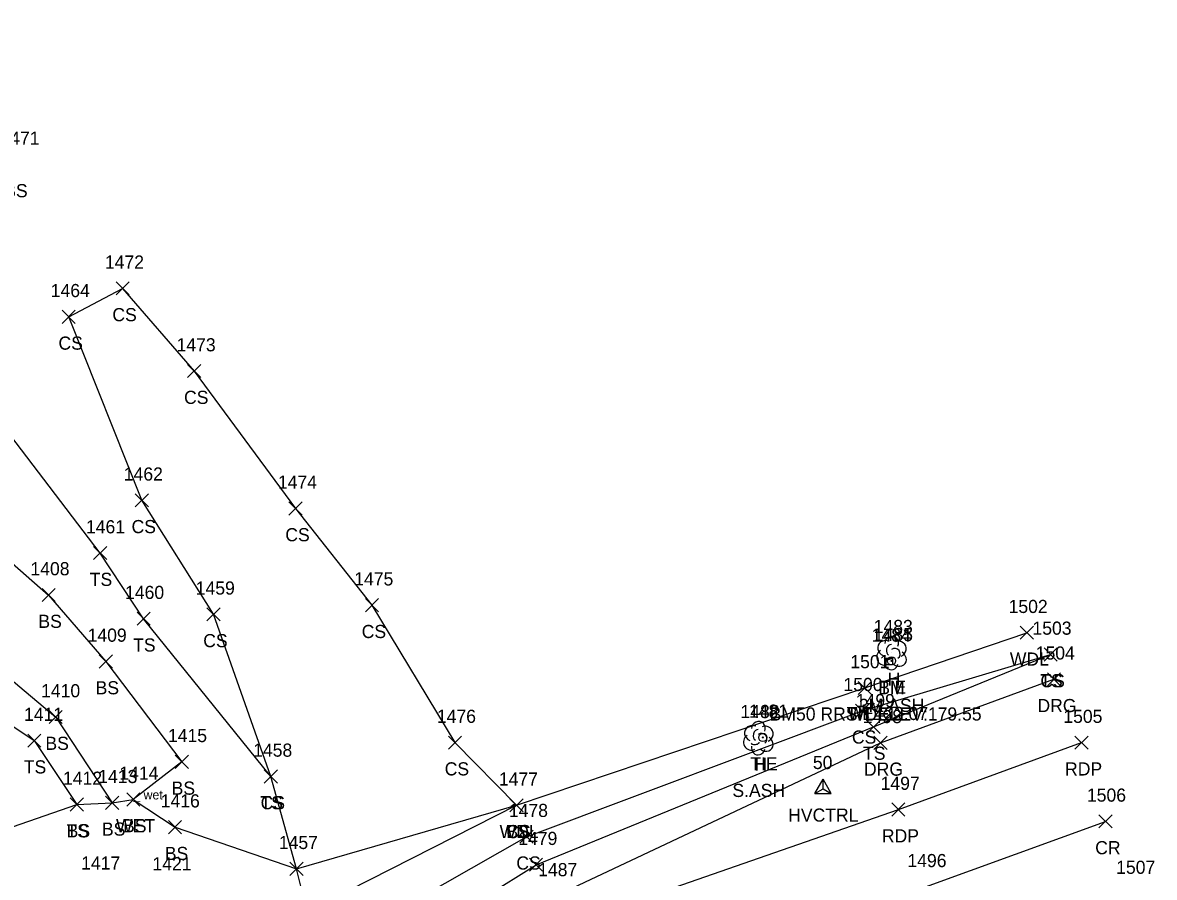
# Model space of a CAD drawing. Extents: x 1443064 to 1445163, y 544063 to 544655.
# Drawn here: x 1443666.1 to 1443838.4, y 544343.6 to 544473.7 of the extents above; entities that cross this region are included whole.
import ezdxf

# ---------------------------------------------------------------- set-up
doc = ezdxf.new("R2010")
doc.units = 0
for name, color, linetype in [('C_A', 7, 'Continuous'), ('C_C', 7, 'Continuous'), ('C_I', 7, 'Continuous'), ('CBP', 7, 'Continuous'), ('CPBM', 7, 'Continuous'), ('CPSM', 7, 'Continuous'), ('L_A', 7, 'Continuous'), ('L_C', 7, 'Continuous'), ('L_I', 7, 'Continuous'), ('L_TIC', 7, 'Continuous'), ('LAWA', 7, 'Continuous'), ('LELB', 7, 'Continuous'), ('LTD', 7, 'Continuous'), ('LWET', 7, 'Continuous'), ('P_A', 7, 'Continuous'), ('P_I', 7, 'Continuous'), ('P_TIC', 7, 'Continuous'), ('PET', 7, 'Continuous'), ('PRC', 7, 'Continuous'), ('R_A', 7, 'Continuous'), ('R_I', 7, 'Continuous'), ('R_TIC', 7, 'Continuous'), ('RDG', 7, 'Continuous')]:
    doc.layers.add(name, color=color, linetype=linetype)

msp = doc.modelspace()

# ---------------------------------------------------------------- linework, layer by layer
at = {"layer": 'CBP'}
for centre, radius in [((1443798.39, 544376.58), 0.625), ((1443798.39, 544376.58), 0.0833), ((1443778.81, 544364.93), 0.625), ((1443778.81, 544364.93), 0.0833)]:
    msp.add_circle(centre, radius, dxfattribs=at)
at = {"layer": 'CPBM'}
for p, q in [((1443797.56, 544376), (1443797.56, 544377)), ((1443797.56, 544377), (1443798.56, 544377)), ((1443798.56, 544376), (1443797.56, 544376)), ((1443798.06, 544376.5), (1443798.06, 544376.5)), ((1443798.06, 544376.5), (1443798.06, 544376.5)), ((1443798.56, 544377), (1443798.56, 544376))]:
    msp.add_line(p, q, dxfattribs=at)
at = {"layer": 'CPSM'}
for p, q in [((1443786.72, 544356.4), (1443787.97, 544358.57)), ((1443789.22, 544356.4), (1443787.97, 544358.57)), ((1443787.97, 544357.12), (1443787.97, 544358.57)), ((1443786.72, 544356.4), (1443787.97, 544357.12)), ((1443787.97, 544357.12), (1443787.97, 544357.12)), ((1443787.97, 544357.12), (1443789.22, 544356.4)), ((1443786.72, 544356.4), (1443789.22, 544356.4))]:
    msp.add_line(p, q, dxfattribs=at)
at = {"layer": 'L_TIC'}
for points in [[(1443680.36, 544432.25), (1443682.36, 544434.25)], [(1443682.36, 544432.25), (1443680.36, 544434.25)], [(1443672.16, 544427.92), (1443674.16, 544429.92)], [(1443674.16, 544427.92), (1443672.16, 544429.92)], [(1443691.26, 544419.67), (1443693.26, 544421.67)], [(1443693.26, 544419.67), (1443691.26, 544421.67)], [(1443683.28, 544400.01), (1443685.28, 544402.01)], [(1443685.28, 544400.01), (1443683.28, 544402.01)], [(1443706.68, 544398.77), (1443708.68, 544400.77)], [(1443708.68, 544398.77), (1443706.68, 544400.77)], [(1443676.95, 544391.98), (1443678.95, 544393.98)], [(1443678.95, 544391.98), (1443676.95, 544393.98)], [(1443669.1, 544385.6), (1443671.1, 544387.6)], [(1443671.1, 544385.6), (1443669.1, 544387.6)], [(1443718.31, 544384.05), (1443720.31, 544386.05)], [(1443720.31, 544384.05), (1443718.31, 544386.05)], [(1443694.19, 544382.66), (1443696.19, 544384.66)], [(1443696.19, 544382.66), (1443694.19, 544384.66)], [(1443683.55, 544382), (1443685.55, 544384)], [(1443685.55, 544382), (1443683.55, 544384)], [(1443817.98, 544379.86), (1443819.98, 544381.86)], [(1443819.98, 544379.86), (1443817.98, 544381.86)], [(1443677.81, 544375.49), (1443679.81, 544377.49)], [(1443679.81, 544375.49), (1443677.81, 544377.49)], [(1443821.61, 544376.56), (1443823.61, 544378.56)], [(1443823.61, 544376.56), (1443821.61, 544378.56)], [(1443821.61, 544376.56), (1443823.61, 544378.56)], [(1443823.61, 544376.56), (1443821.61, 544378.56)], [(1443793.32, 544371.46), (1443795.32, 544373.46)], [(1443795.32, 544371.46), (1443793.32, 544373.46)], [(1443670.17, 544367.04), (1443672.17, 544369.04)], [(1443672.17, 544367.04), (1443670.17, 544369.04)], [(1443792.92, 544367.99), (1443794.92, 544369.99)], [(1443794.92, 544367.99), (1443792.92, 544369.99)], [(1443794.65, 544365.53), (1443796.65, 544367.53)], [(1443796.65, 544365.53), (1443794.65, 544367.53)], [(1443666.92, 544363.45), (1443668.92, 544365.45)], [(1443668.92, 544363.45), (1443666.92, 544365.45)], [(1443730.94, 544363.15), (1443732.94, 544365.15)], [(1443732.94, 544363.15), (1443730.94, 544365.15)], [(1443689.38, 544360.22), (1443691.38, 544362.22)], [(1443691.38, 544360.22), (1443689.38, 544362.22)], [(1443702.92, 544358), (1443704.92, 544360)], [(1443704.92, 544358), (1443702.92, 544360)], [(1443702.92, 544358), (1443704.92, 544360)], [(1443704.92, 544358), (1443702.92, 544360)], [(1443673.4, 544353.73), (1443675.4, 544355.73)], [(1443675.4, 544353.73), (1443673.4, 544355.73)], [(1443673.4, 544353.73), (1443675.4, 544355.73)], [(1443675.4, 544353.73), (1443673.4, 544355.73)], [(1443678.77, 544353.99), (1443680.77, 544355.99)], [(1443680.77, 544353.99), (1443678.77, 544355.99)], [(1443678.77, 544353.99), (1443680.77, 544355.99)], [(1443680.77, 544353.99), (1443678.77, 544355.99)], [(1443681.99, 544354.5), (1443683.99, 544356.5)], [(1443683.99, 544354.5), (1443681.99, 544356.5)], [(1443740.32, 544353.61), (1443742.32, 544355.61)], [(1443742.32, 544353.61), (1443740.32, 544355.61)], [(1443740.32, 544353.61), (1443742.32, 544355.61)], [(1443742.32, 544353.61), (1443740.32, 544355.61)], [(1443740.32, 544353.61), (1443742.32, 544355.61)], [(1443742.32, 544353.61), (1443740.32, 544355.61)], [(1443688.34, 544350.28), (1443690.34, 544352.28)], [(1443690.34, 544350.28), (1443688.34, 544352.28)], [(1443741.84, 544348.83), (1443743.84, 544350.83)], [(1443743.84, 544348.83), (1443741.84, 544350.83)], [(1443743.28, 544344.57), (1443745.28, 544346.57)], [(1443745.28, 544344.57), (1443743.28, 544346.57)], [(1443706.83, 544343.95), (1443708.83, 544345.95)], [(1443708.83, 544343.95), (1443706.83, 544345.95)], [(1443706.83, 544343.95), (1443708.83, 544345.95)], [(1443708.83, 544343.95), (1443706.83, 544345.95)]]:
    msp.add_lwpolyline(points, dxfattribs=at)
at = {"layer": 'LAWA'}
msp.add_lwpolyline([(1443161.29, 544157.23), (1443186.09, 544163.69), (1443194.34, 544166.63), (1443196.33, 544167.63), (1443201.36, 544168), (1443240.97, 544179.17), (1443262.42, 544188.86), (1443303.08, 544207.19), (1443347.02, 544222.79), (1443391.79, 544240.14), (1443432.68, 544254.71), (1443466.61, 544275.19), (1443493.21, 544282.75), (1443512.25, 544287.37), (1443549.07, 544304.36), (1443598.9, 544317.54), (1443643.36, 544329.59), (1443677.18, 544341.83), (1443688.03, 544341.71), (1443709.45, 544338.47), (1443741.32, 544354.61), (1443794.32, 544372.46), (1443818.98, 544380.86)], dxfattribs=at)
at = {"layer": 'LELB'}
for points in [[(1443703.92, 544359), (1443684.55, 544383), (1443677.95, 544392.98), (1443659.94, 544416.54), (1443646.5, 544427.52), (1443636.89, 544438.13), (1443634.15, 544445.26), (1443648.73, 544473.67)], [(1443623.82, 544449.76), (1443627.68, 544433.27), (1443634.47, 544420.35), (1443646.64, 544407.16), (1443670.1, 544386.6), (1443678.81, 544376.49), (1443690.38, 544361.22)], [(1443709.45, 544338.47), (1443707.83, 544344.95), (1443703.92, 544359), (1443695.19, 544383.66), (1443684.28, 544401.01), (1443673.16, 544428.92), (1443681.36, 544433.25), (1443692.26, 544420.67), (1443707.68, 544399.77), (1443719.31, 544385.05), (1443731.94, 544364.15), (1443741.32, 544354.61)], [(1443524.64, 544310.64), (1443516.19, 544326.6), (1443510.31, 544349.8), (1443515.95, 544360.33), (1443522.99, 544376.07), (1443544.45, 544389.43), (1443567.81, 544396.05), (1443579.35, 544394.62), (1443599.52, 544398.63), (1443597.31, 544382.32), (1443586.08, 544366.03), (1443577.64, 544350.42), (1443570.87, 544335.45), (1443571.67, 544335.89), (1443585.93, 544349.75), (1443593.9, 544362.32), (1443625.57, 544387.61), (1443642.36, 544389.68), (1443660.17, 544377.25), (1443671.17, 544368.04), (1443679.77, 544354.99)], [(1443524.64, 544310.64), (1443526.32, 544324.86), (1443524.94, 544337.03), (1443526.8, 544352.97), (1443533.03, 544366.39), (1443555.27, 544377.24), (1443570.07, 544381.21), (1443577.35, 544375.95), (1443572.02, 544357.68), (1443563.05, 544332.87), (1443565.18, 544320.82), (1443576.27, 544327.45), (1443588.87, 544344.43), (1443596.53, 544354.68), (1443629.38, 544373.37), (1443639.2, 544382.04), (1443656.76, 544371.94), (1443667.92, 544364.45), (1443674.4, 544354.73)], [(1443073.59, 544128.34), (1443116.66, 544141.89), (1443162.8, 544149.75), (1443198.07, 544157.24), (1443242.5, 544173.41), (1443262.84, 544182.05), (1443307.11, 544199.46), (1443348.85, 544214.35), (1443394.74, 544233.02), (1443435.02, 544243.93), (1443473.16, 544259.47), (1443514.32, 544272.16), (1443555.56, 544285.54), (1443605.06, 544302.52), (1443644.56, 544313.72), (1443676.09, 544324.26), (1443689.45, 544326.75), (1443708.55, 544330.01), (1443714.07, 544333.45), (1443742.84, 544349.83), (1443793.92, 544368.99), (1443822.61, 544377.56)], [(1443074.67, 544122.4), (1443120.32, 544131.74), (1443165.11, 544143.77), (1443199.58, 544153.13), (1443245.24, 544167.88), (1443264.59, 544177.57), (1443308.86, 544194.48), (1443350.56, 544209.36), (1443397.32, 544225.82), (1443437.1, 544238.98), (1443476.53, 544253.14), (1443516.75, 544265.8), (1443558.95, 544280.95), (1443607.52, 544296.39), (1443646.45, 544306.32), (1443685.12, 544319.06), (1443714.26, 544329.16), (1443721.31, 544331.26), (1443744.28, 544345.57), (1443795.65, 544366.53), (1443822.61, 544377.56)], [(1443690.38, 544361.22), (1443682.99, 544355.5)], [(1443298.3, 544219.12), (1443343.36, 544234.64), (1443347.13, 544235.69), (1443361.65, 544240.04), (1443373.89, 544246.37), (1443387.28, 544254.4), (1443426.15, 544267.88), (1443461.49, 544286.76), (1443487.3, 544295.55), (1443508.64, 544301.52), (1443524.64, 544310.64), (1443543.83, 544318.46), (1443565.18, 544320.82), (1443579.86, 544324.28), (1443590.71, 544328.22), (1443606.37, 544329.69), (1443641.44, 544343.33), (1443674.4, 544354.73), (1443679.77, 544354.99), (1443682.99, 544355.5), (1443689.34, 544351.28), (1443707.83, 544344.95), (1443741.32, 544354.61)]]:
    msp.add_lwpolyline(points, dxfattribs=at)
at = {"layer": 'LTD'}
for p, q in [((1443798.37, 544377.81), (1443798.37, 544377.81)), ((1443798.37, 544377.81), (1443798.37, 544377.81)), ((1443778.09, 544364.87), (1443778.09, 544364.87)), ((1443778.09, 544364.87), (1443778.09, 544364.87))]:
    msp.add_line(p, q, dxfattribs=at)
for centre in [(1443798.42, 544379.24), (1443778.14, 544366.31)]:
    msp.add_arc(centre, 1.05, 335.5272, 180.9563, dxfattribs=at)
for centre, major_axis, ratio, start_param, end_param in [((1443797.58, 544378.47), (1.21, -0.51), 0.895232, 1.570796, 4.712389), ((1443798.16, 544378.26), (-0.208, -0.792), 0.645439, 3.141593, 6.283185), ((1443799.41, 544378.39), (-1.14, -0.48), 0.949671, 1.570796, 4.712389), ((1443797.29, 544377.1), (0.58, -1.04), 0.959034, 3.141593, 6.283185), ((1443798.87, 544377.64), (-0.5, 0.667), 0.989748, 3.141593, 6.283185), ((1443799.37, 544376.97), (-1.09, 0.79), 0.841452, 1.570796, 4.712389), ((1443798.37, 544376.31), (0.26, 1.06), 0.942809, 1.570796, 4.712389), ((1443797.91, 544377.06), (-0.625, -0.083), 0.423636, 0, 3.141593), ((1443777.3, 544365.54), (1.21, -0.51), 0.895232, 1.570796, 4.712389), ((1443777.01, 544364.17), (0.58, -1.04), 0.959034, 3.141593, 6.283185), ((1443777.89, 544365.33), (-0.208, -0.792), 0.645439, 3.141593, 6.283185), ((1443778.59, 544364.71), (-0.5, 0.667), 0.989748, 3.141593, 6.283185), ((1443779.14, 544365.46), (-1.14, -0.48), 0.949671, 1.570796, 4.712389), ((1443778.1, 544363.37), (0.26, 1.06), 0.942809, 1.570796, 4.712389), ((1443777.64, 544364.12), (-0.625, -0.083), 0.423636, 0, 3.141593), ((1443779.09, 544364.04), (-1.09, 0.79), 0.841452, 1.570796, 4.712389)]:
    msp.add_ellipse(centre, major_axis=major_axis, ratio=ratio, start_param=start_param, end_param=end_param, dxfattribs=at)
at = {"layer": 'P_TIC'}
for points in [[(1443826.31, 544363.14), (1443828.31, 544365.14)], [(1443828.31, 544363.14), (1443826.31, 544365.14)], [(1443798.43, 544352.96), (1443800.43, 544354.96)], [(1443800.43, 544352.96), (1443798.43, 544354.96)], [(1443829.96, 544351.16), (1443831.96, 544353.16)], [(1443831.96, 544351.16), (1443829.96, 544353.16)]]:
    msp.add_lwpolyline(points, dxfattribs=at)
at = {"layer": 'PET'}
msp.add_lwpolyline([(1443075.39, 544117.71), (1443121.41, 544129.24), (1443165.99, 544140.07), (1443200.71, 544149.88), (1443246.42, 544165.39), (1443265.96, 544172.48), (1443311.2, 544187.88), (1443352.92, 544202.76), (1443399.28, 544220.13), (1443438.78, 544233.67), (1443478.75, 544247.35), (1443518.41, 544260.6), (1443561.23, 544274.05), (1443611.7, 544290.5), (1443646.84, 544301.68), (1443684.98, 544314.55), (1443724.57, 544327.54), (1443735.41, 544331.22), (1443748.81, 544336.36), (1443799.43, 544353.96), (1443827.31, 544364.14)], dxfattribs=at)
at = {"layer": 'PRC'}
msp.add_lwpolyline([(1443078.47, 544103.68), (1443125.02, 544115.93), (1443169.41, 544128.22), (1443204.47, 544139.4), (1443250.36, 544154.3), (1443269.99, 544160.83), (1443315.13, 544176.71), (1443356.58, 544191.19), (1443403.59, 544208.05), (1443442.67, 544222.02), (1443482.15, 544235.41), (1443522.16, 544248.37), (1443565.47, 544262.64), (1443616.51, 544279.34), (1443650.9, 544289.93), (1443689.58, 544302.53), (1443728.44, 544315.77), (1443753.53, 544324.68), (1443803.56, 544342.2), (1443830.96, 544352.16)], dxfattribs=at)
at = {"layer": 'R_TIC'}
for points in [[(1443822.11, 544372.78), (1443824.11, 544374.78)], [(1443824.11, 544372.78), (1443822.11, 544374.78)], [(1443795.71, 544363.11), (1443797.71, 544365.11)], [(1443797.71, 544363.11), (1443795.71, 544365.11)]]:
    msp.add_lwpolyline(points, dxfattribs=at)
at = {"layer": 'RDG'}
msp.add_lwpolyline([(1443735.41, 544331.22), (1443747.3, 544340.82), (1443796.71, 544364.11), (1443823.11, 544373.78)], dxfattribs=at)

# ---------------------------------------------------------------- texts
at = {"layer": 'C_A'}
for s, p in [('TIE', (1443796.47, 544371.58)), ('BM', (1443796.38, 544371.5)), ('TIE', (1443776.89, 544359.93)), ('HVCTRL', (1443782.66, 544352.12))]:
    msp.add_text(s, height=2, dxfattribs=at).set_placement(p)
at = {"layer": 'C_C'}
for s, p in [('BM50 RRSIT ELEV:179.55', (1443779.84, 544367.5)), ('TIE=22.07', (1443791.54, 544367.58))]:
    msp.add_text(s, height=2, dxfattribs=at).set_placement(p)
at = {"layer": 'C_I'}
for s, p in [('1484', (1443795.37, 544379.5)), ('1485', (1443795.7, 544379.58)), ('1481', (1443776.69, 544367.93)), ('50', (1443786.42, 544360.12))]:
    msp.add_text(s, height=2, dxfattribs=at).set_placement(p)
at = {"layer": 'L_A'}
for s, p in [('BS', (1443663.34, 544447.11)), ('CS', (1443679.8, 544428.25)), ('CS', (1443671.6, 544423.92)), ('CS', (1443690.71, 544415.67)), ('CS', (1443682.72, 544396.01)), ('CS', (1443706.12, 544394.77)), ('TS', (1443676.36, 544387.98)), ('BS', (1443668.54, 544381.6)), ('CS', (1443693.63, 544378.66)), ('CS', (1443717.75, 544380.05)), ('TS', (1443682.96, 544378)), ('WDL', (1443816.4, 544375.86)), ('H', (1443797.8, 544372.81)), ('TS', (1443821.02, 544372.56)), ('CS', (1443821.05, 544372.56)), ('BS', (1443677.25, 544371.49)), ('WDL', (1443791.74, 544367.46)), ('CS', (1443792.36, 544363.99)), ('BS', (1443669.61, 544363.04)), ('TS', (1443794.06, 544361.53)), ('H', (1443777.53, 544359.87)), ('TS', (1443666.32, 544359.45)), ('CS', (1443730.38, 544359.15)), ('BS', (1443688.82, 544356.22)), ('TS', (1443702.33, 544354)), ('CS', (1443702.36, 544354)), ('TS', (1443672.81, 544349.73)), ('BS', (1443672.84, 544349.73)), ('BS', (1443678.21, 544349.99)), ('BS', (1443678.21, 544349.99)), ('WET', (1443680.36, 544350.5)), ('BS', (1443681.43, 544350.5)), ('WDL', (1443738.74, 544349.61)), ('CS', (1443739.76, 544349.61)), ('BS', (1443739.76, 544349.61)), ('BS', (1443687.78, 544346.28)), ('CS', (1443741.28, 544344.83))]:
    msp.add_text(s, height=2, dxfattribs=at).set_placement(p)
at = {"layer": 'L_C'}
for s, p in [('3M.ASH', (1443793.43, 544368.81)), ('S.ASH', (1443774.17, 544355.87))]:
    msp.add_text(s, height=2, dxfattribs=at).set_placement(p)
at = {"layer": 'L_I'}
for s, p in [('1471', (1443662.77, 544455.11)), ('1472', (1443678.66, 544436.25)), ('1464', (1443670.42, 544431.92)), ('1473', (1443689.57, 544423.67)), ('1462', (1443681.54, 544404.01)), ('1474', (1443704.99, 544402.77)), ('1461', (1443675.78, 544395.98)), ('1408', (1443667.33, 544389.6)), ('1475', (1443716.61, 544388.05)), ('1460', (1443681.73, 544386)), ('1459', (1443692.49, 544386.66)), ('1502', (1443816.21, 544383.86)), ('1483', (1443795.68, 544380.81)), ('1503', (1443819.84, 544380.56)), ('1503', (1443819.84, 544380.56)), ('1409', (1443676.03, 544379.49)), ('1501', (1443792.12, 544375.46)), ('1500', (1443791.07, 544371.99)), ('1410', (1443668.95, 544371.04)), ('1499', (1443792.95, 544369.53)), ('1411', (1443666.36, 544367.45)), ('1476', (1443729.19, 544367.15)), ('1482', (1443775.4, 544367.87)), ('1415', (1443688.26, 544364.22)), ('1458', (1443701.23, 544362)), ('1458', (1443701.23, 544362)), ('1413', (1443677.65, 544357.99)), ('1413', (1443677.65, 544357.99)), ('1414', (1443680.86, 544358.5)), ('1414', (1443680.86, 544358.5)), ('1412', (1443672.28, 544357.73)), ('1412', (1443672.28, 544357.73)), ('1477', (1443738.63, 544357.61)), ('1477', (1443738.63, 544357.61)), ('1477', (1443738.63, 544357.61)), ('1416', (1443687.16, 544354.28)), ('1478', (1443740.15, 544352.83)), ('1457', (1443705.14, 544347.95)), ('1457', (1443705.14, 544347.95)), ('1479', (1443741.58, 544348.57)), ('1417', (1443675.05, 544344.83)), ('1421', (1443685.9, 544344.71))]:
    msp.add_text(s, height=2, dxfattribs=at).set_placement(p)
at = {"layer": 'LWET'}
msp.add_text('_ wet', height=1.4, dxfattribs=at).set_placement((1443682.99, 544355.5))
at = {"layer": 'P_A'}
for s, p in [('RDP', (1443824.8, 544359.14)), ('RDP', (1443796.92, 544348.96)), ('CR', (1443829.39, 544347.16))]:
    msp.add_text(s, height=2, dxfattribs=at).set_placement(p)
at = {"layer": 'P_I'}
for s, p in [('1505', (1443824.54, 544367.14)), ('1497', (1443796.73, 544356.96)), ('1506', (1443828.13, 544355.16)), ('1496', (1443800.81, 544345.2)), ('1507', (1443832.58, 544344.18))]:
    msp.add_text(s, height=2, dxfattribs=at).set_placement(p)
at = {"layer": 'R_A'}
for p in [(1443820.6, 544368.78), (1443794.2, 544359.11)]:
    msp.add_text('DRG', height=2, dxfattribs=at).set_placement(p)
at = {"layer": 'R_I'}
for s, p in [('1504', (1443820.34, 544376.78)), ('1498', (1443794.02, 544367.11)), ('1487', (1443744.61, 544343.82))]:
    msp.add_text(s, height=2, dxfattribs=at).set_placement(p)

doc.saveas('drawing.dxf')
